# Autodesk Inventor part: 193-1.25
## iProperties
Created: 2007-06
Part Number: 193-1.25
Document SubType Name: Modeling
Designer: btaylor
Density: 1 g/cm^3
Author: btaylor
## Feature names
1. Sweep1
2. Extrusion1
3. Extrusion2
4. Extrusion3
5. Extrusion4
6. Sweep2
7. Fillet1
8. Fillet2
9. Fillet3
10. Fillet4
11. Chamfer1
12. Chamfer2
13. Fillet5
14. Fillet6
